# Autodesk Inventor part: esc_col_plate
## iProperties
Shininess: 64.0
Length Units: 11269
Angle Units: 11279
Time Units: 11290
Mass Units: 11283
Length Display Precision: 3
Angle Display Precision: 2
Compacted: True
Part Number: esc_col_plate
Document SubType Name: Modeling
Created: 2004-08
Designer: John Blackburn
Manufacturer: Standard
Standards Organization: Custom
Material: Aluminum-6061
Density: 0.0
Volumn: 0.0
Area: 0.0
PropertySet Name: Model Information
Control State: 0
Master: False
Checked Out: False
Author: John Blackburn
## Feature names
1. Extrusion1
2. Extrusion2
3. Hole2
4. Fillet1
